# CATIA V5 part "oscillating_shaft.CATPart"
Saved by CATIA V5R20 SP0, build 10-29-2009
Part number: OscillatingShaft
Bounding box of the stored display mesh (mm): x -16 to 16, y -15.912 to 15.994, z 0 to 356
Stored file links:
  D:\OneDrive\OneDrive - 한양대학교\문서\Teaching\2021\CAD\Final Exam\oscillation motion\oscilating_shaft.CATPart
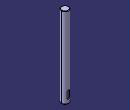
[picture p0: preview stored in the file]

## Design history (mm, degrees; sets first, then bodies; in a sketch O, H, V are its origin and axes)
Body1 (main body)
  Sketch1 on xy-plane, origin (0, 0, 0), H (1, 0, 0), V (0, 1, 0)
    circle A1 centre (0, 0) radius 16
    radius A1 = 16
  Pad1: profile Sketch1, direction (0, 0, 1), length 356
  Chamfer1: length 2, angle 45, on edge [face of Pad1 from Sketch1.A1 | end face of Pad1]
  Chamfer2: length 2, angle 45, on start face of Pad1
  Plane1: type Offset, RefPlane zx-plane, Offset 20
  Sketch2 on Plane1, origin (0, 20, 0), H (-1, 0, 0), V (0, 0, 1)
    arc A1 centre (0, 48) radius 5 from (5, 48) to (-5, 48) ccw
    arc A2 centre (0, 22) radius 5 from (-5, 22) to (5, 22) ccw
    point P2 (0, 22)
    line L1 (-5, 48) -> (-5, 22)
    line L2 (5, 48) -> (5, 22)
    reference intersected line E1 through (0, 0) direction (-1, 0) from xy-plane
    distance E1 P2 = 22
    radius A2 = 5
    distance A2 A1 = 36
    tangency: L2 A1, L1 A1, L1 A2, L2 A2
    vertical: L2 V, L1 V
    coincidence: P2 V
  Pocket1: profile Sketch2, direction (0, -1, 0), length 8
